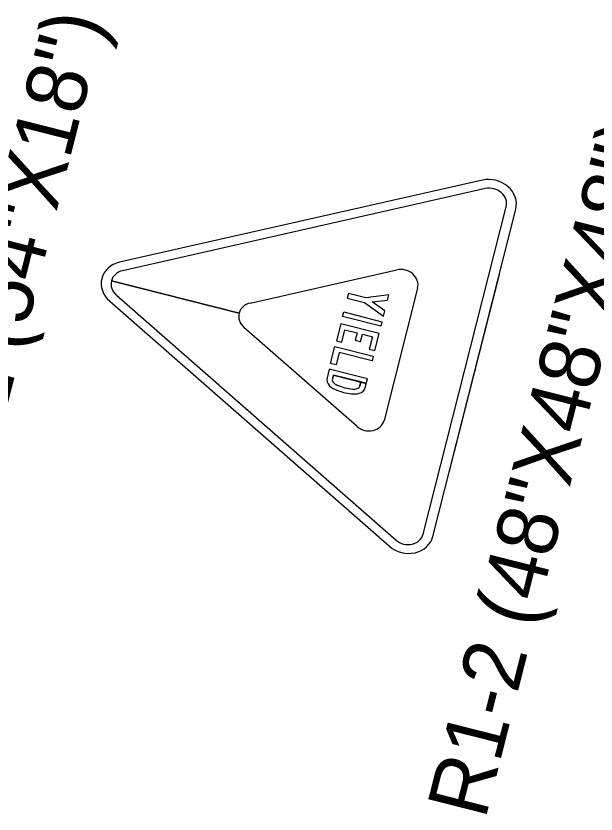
# Model space of a CAD drawing. Extents: x 670257 to 671518, y 737783 to 738188.
# Drawn here: x 670289.572 to 670291.975, y 738130.728 to 738134.035 of the extents above; entities that cross this region are included whole.
import ezdxf

# ---------------------------------------------------------------- set-up
doc = ezdxf.new("R2010")
doc.units = 0
doc.layers.add('Default', color=7, linetype='Continuous')
doc.layers.add('R_SIGN_HWY72', color=7, linetype='Continuous')

msp = doc.modelspace()

# ---------------------------------------------------------------- linework, layer by layer
at = {"layer": 'R_SIGN_HWY72'}
for p, q in [((670291.5043, 738133.3552), (670290.0014, 738133.0149)), ((670291.5043, 738133.3552), (670291.5043, 738133.3552)), ((670291.5164, 738133.3199), (670290.0136, 738132.9795)), ((670291.5164, 738133.3199), (670291.5164, 738133.3199)), ((670291.2588, 738131.8884), (670291.6028, 738133.2443)), ((670291.2984, 738131.8783), (670291.6424, 738133.2342)), ((670291.2984, 738131.8783), (670291.6424, 738133.2342)), ((670291.6028, 738133.2443), (670291.6027, 738133.2443)), ((670290.0014, 738133.0149), (670290.0014, 738133.0149)), ((670290.5422, 738132.8454), (670291.1496, 738132.983)), ((670291.1496, 738132.983), (670291.1497, 738132.983)), ((670290.0136, 738132.9795), (670290.0136, 738132.9795)), ((670291.5736, 738132.9633), (670291.3672, 738132.1493)), ((670290.4963, 738132.8033), (670289.9677, 738132.9374)), ((670289.9677, 738132.9374), (670289.9677, 738132.9374)), ((670289.9678, 738132.9379), (670289.9678, 738132.9379)), ((670289.9678, 738132.9379), (670290.4965, 738132.8038)), ((670291.236, 738132.9074), (670291.097, 738132.3593)), ((670291.236, 738132.9074), (670291.236, 738132.9074)), ((670289.9604, 738132.8533), (670289.9605, 738132.8533)), ((670289.9605, 738132.8533), (670291.1194, 738131.8378)), ((670289.9605, 738132.8533), (670291.1194, 738131.8378)), ((670289.988, 738132.8786), (670289.988, 738132.8785)), ((670289.988, 738132.8785), (670291.1469, 738131.8631)), ((670290.4963, 738132.8033), (670290.4963, 738132.8033)), ((670290.4965, 738132.8038), (670290.4965, 738132.8038)), ((670290.5166, 738132.7444), (670290.5166, 738132.7445)), ((670290.985, 738132.334), (670290.5166, 738132.7444)), ((670291.097, 738132.3593), (670291.097, 738132.3593)), ((670290.985, 738132.334), (670290.985, 738132.334)), ((670291.1469, 738131.8631), (670291.1469, 738131.863)), ((670291.2588, 738131.8884), (670291.2588, 738131.8884)), ((670291.2985, 738131.8783), (670291.2984, 738131.8783)), ((670291.2985, 738131.8783), (670291.2984, 738131.8783)), ((670291.1194, 738131.8378), (670291.1194, 738131.8378))]:
    msp.add_line(p, q, dxfattribs=at)
for points in [[(670291.1164, 738132.8793), (670291.0208, 738132.8673), (670290.9491, 738132.8855), (670290.9442, 738132.8662), (670291.0159, 738132.848), (670291.0942, 738132.7918), (670291.0996, 738132.813), (670291.0477, 738132.8502), (670291.111, 738132.8581)], [(670291.1164, 738132.8793), (670291.0208, 738132.8673), (670290.9491, 738132.8855), (670290.9442, 738132.8662), (670291.0159, 738132.848), (670291.0942, 738132.7918), (670291.0996, 738132.813), (670291.0477, 738132.8502), (670291.111, 738132.8581)], [(670291.1164, 738132.8793), (670291.0208, 738132.8673), (670290.9491, 738132.8855), (670290.9442, 738132.8662), (670291.0159, 738132.848), (670291.0942, 738132.7918), (670291.0996, 738132.813), (670291.0477, 738132.8502), (670291.111, 738132.8581)], [(670291.0883, 738132.7684), (670291.0834, 738132.7491), (670290.9247, 738132.7893), (670290.9296, 738132.8086)], [(670291.0883, 738132.7684), (670291.0834, 738132.7491), (670290.9247, 738132.7893), (670290.9296, 738132.8086)], [(670291.0883, 738132.7684), (670291.0834, 738132.7491), (670290.9247, 738132.7893), (670290.9296, 738132.8086)], [(670290.9345, 738132.7347), (670290.9853, 738132.7219), (670290.9776, 738132.6917), (670290.9998, 738132.686), (670291.0075, 738132.7162), (670291.0487, 738132.7058), (670291.0358, 738132.6548), (670291.058, 738132.6492), (670291.0759, 738132.7194), (670290.9172, 738132.7597), (670290.8994, 738132.6894), (670290.9216, 738132.6838)], [(670290.9345, 738132.7347), (670290.9853, 738132.7219), (670290.9776, 738132.6917), (670290.9998, 738132.686), (670291.0075, 738132.7162), (670291.0487, 738132.7058), (670291.0358, 738132.6548), (670291.058, 738132.6492), (670291.0759, 738132.7194), (670290.9172, 738132.7597), (670290.8994, 738132.6894), (670290.9216, 738132.6838)], [(670290.9345, 738132.7347), (670290.9853, 738132.7219), (670290.9776, 738132.6917), (670290.9998, 738132.686), (670291.0075, 738132.7162), (670291.0487, 738132.7058), (670291.0358, 738132.6548), (670291.058, 738132.6492), (670291.0759, 738132.7194), (670290.9172, 738132.7597), (670290.8994, 738132.6894), (670290.9216, 738132.6838)], [(670291.0521, 738132.6257), (670291.0472, 738132.6064), (670290.9108, 738132.641), (670290.8978, 738132.5901), (670290.8756, 738132.5957), (670290.8934, 738132.666)], [(670291.0521, 738132.6257), (670291.0472, 738132.6064), (670290.9108, 738132.641), (670290.8978, 738132.5901), (670290.8756, 738132.5957), (670290.8934, 738132.666)], [(670291.0521, 738132.6257), (670291.0472, 738132.6064), (670290.9108, 738132.641), (670290.8978, 738132.5901), (670290.8756, 738132.5957), (670290.8934, 738132.666)]]:
    msp.add_lwpolyline(points, close=True, dxfattribs=at)
for points in [[(670291.0192, 738132.4961), (670291.0283, 738132.532), (670290.8697, 738132.5722), (670290.8648, 738132.553), (670290.8606, 738132.5363)], [(670290.8828, 738132.5307), (670290.887, 738132.5473), (670291.0234, 738132.5127), (670291.0283, 738132.532), (670290.8697, 738132.5722), (670290.8648, 738132.553), (670290.8606, 738132.5363)], [(670290.8828, 738132.5307), (670290.887, 738132.5473), (670291.0234, 738132.5127), (670291.0283, 738132.532), (670290.8697, 738132.5722), (670290.8648, 738132.553), (670290.8606, 738132.5363)], [(670290.997, 738132.5017), (670291.0012, 738132.5184), (670290.887, 738132.5473), (670290.8828, 738132.5307)], [(670291.0192, 738132.4961), (670291.0234, 738132.5127), (670291.0012, 738132.5184), (670290.997, 738132.5017)], [(670291.0192, 738132.4961), (670291.0234, 738132.5127), (670291.0012, 738132.5184), (670290.997, 738132.5017)]]:
    msp.add_lwpolyline(points, dxfattribs=at)
for centre, major_axis, ratio, start_param, end_param in [((670291.5367, 738133.261), (0.1057, -0.0268), 0.881924, 0, 2.094395), ((670291.5367, 738133.261), (0.0661, -0.0168), 0.881924, 0, 2.094395), ((670290.0338, 738132.9207), (0.1058, -0.0268), 0.881924, 2.094222, 4.188617), ((670291.1699, 738132.9242), (0.0661, -0.0168), 0.881924, 6.283012, 8.377407), ((670290.0338, 738132.9207), (0.0661, -0.0168), 0.881924, 2.094222, 3.133419), ((670290.0338, 738132.9207), (0.0661, -0.0168), 0.881924, 3.141593, 4.18879), ((670290.5624, 738132.7866), (0.0661, -0.0168), 0.881924, 2.094392, 3.133589), ((670290.5624, 738132.7866), (0.0661, -0.0168), 0.881924, 3.141766, 4.188963), ((670290.8981, 738132.5259), (0.0378, -0.0096), 0.868695, 3.114503, 4.168149), ((670290.8981, 738132.5259), (0.0378, -0.0096), 0.868695, 3.114503, 4.168149), ((670290.8981, 738132.5259), (0.0378, -0.0096), 0.868695, 3.114503, 4.168149), ((670290.8999, 738132.5264), (0.0172, -0.0044), 0.868695, 3.142776, 4.129094), ((670290.8999, 738132.5264), (0.0172, -0.0044), 0.868695, 3.142776, 4.129094), ((670290.8999, 738132.5264), (0.0172, -0.0044), 0.868695, 3.142776, 4.129094), ((670290.9185, 738132.5378), (0.0622, -0.0158), 0.868695, 4.097883, 4.614782), ((670290.9185, 738132.5378), (0.0622, -0.0158), 0.868695, 4.097883, 4.614782), ((670290.9185, 738132.5378), (0.0622, -0.0158), 0.868695, 4.097883, 4.614782), ((670290.9152, 738132.5337), (0.0344, -0.0087), 0.868695, 4.017615, 4.575378), ((670290.9152, 738132.5337), (0.0344, -0.0087), 0.868695, 4.017615, 4.575378), ((670290.9152, 738132.5337), (0.0344, -0.0087), 0.868695, 4.017615, 4.575378), ((670290.992, 738132.7051), (0.2433, -0.0617), 0.868695, 4.563596, 4.696012), ((670290.992, 738132.7051), (0.2433, -0.0617), 0.868695, 4.563596, 4.696012), ((670290.992, 738132.7051), (0.2433, -0.0617), 0.868695, 4.563596, 4.696012), ((670290.9841, 738132.7071), (0.2433, -0.0617), 0.868695, 4.728766, 4.861182), ((670290.9841, 738132.7071), (0.2433, -0.0617), 0.868695, 4.728766, 4.861182), ((670290.9841, 738132.7071), (0.2433, -0.0617), 0.868695, 4.728766, 4.861182), ((670290.9699, 738132.5198), (0.0344, -0.0087), 0.868695, 4.8494, 5.407163), ((670290.9699, 738132.5198), (0.0344, -0.0087), 0.868695, 4.8494, 5.407163), ((670290.9699, 738132.5198), (0.0344, -0.0087), 0.868695, 4.8494, 5.407163), ((670290.9798, 738132.5061), (0.0172, -0.0044), 0.868695, 5.295684, 6.282002), ((670290.9798, 738132.5061), (0.0172, -0.0044), 0.868695, 5.295684, 6.282002), ((670290.9798, 738132.5061), (0.0172, -0.0044), 0.868695, 5.295684, 6.282002), ((670290.9812, 738132.5048), (0.0378, -0.0096), 0.868695, 5.256629, 6.310275), ((670290.9812, 738132.5048), (0.0378, -0.0096), 0.868695, 5.256629, 6.310275), ((670290.9812, 738132.5048), (0.0378, -0.0096), 0.868695, 5.256629, 6.310275), ((670290.9741, 738132.6499), (0.201, -0.051), 0.868695, 4.554523, 4.710899), ((670290.9741, 738132.6499), (0.201, -0.051), 0.868695, 4.554523, 4.710899), ((670290.9741, 738132.6499), (0.201, -0.051), 0.868695, 4.554523, 4.710899), ((670290.9735, 738132.6501), (0.201, -0.051), 0.868695, 4.713879, 4.870255), ((670290.9735, 738132.6501), (0.201, -0.051), 0.868695, 4.713879, 4.870255), ((670290.9735, 738132.6501), (0.201, -0.051), 0.868695, 4.713879, 4.870255), ((670290.969, 738132.525), (0.0622, -0.0158), 0.868695, 4.809996, 5.326895), ((670290.969, 738132.525), (0.0622, -0.0158), 0.868695, 4.809996, 5.326895), ((670290.969, 738132.525), (0.0622, -0.0158), 0.868695, 4.809996, 5.326895), ((670291.0309, 738132.3761), (0.0661, -0.0168), 0.881924, 4.18879, 6.283185), ((670291.1927, 738131.9051), (0.1058, -0.0268), 0.881924, 4.188963, 6.283358), ((670291.1927, 738131.9051), (0.1058, -0.0268), 0.881924, 4.188963, 6.283358), ((670291.1927, 738131.9051), (0.0661, -0.0168), 0.881924, 4.188963, 6.283358)]:
    msp.add_ellipse(centre, major_axis=major_axis, ratio=ratio, start_param=start_param, end_param=end_param, dxfattribs=at)

# ---------------------------------------------------------------- texts
at = {"layer": 'Default'}
for s, p in [('R6-1L (54"X18")', (670289.3446, 738131.6642)), ('R1-2 (48"X48"X48")', (670291.5157, 738130.7013))]:
    msp.add_text(s, height=0.25, rotation=75.7686, dxfattribs=at).set_placement(p)

doc.saveas('drawing.dxf')
